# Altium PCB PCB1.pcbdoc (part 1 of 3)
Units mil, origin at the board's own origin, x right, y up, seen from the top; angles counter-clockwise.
Board outline 1393.7 x 1462.72 mil, 2 copper layers (Top Layer, Bottom Layer), stack 62.206 mil thick; 10 components, 35 nets, 86 pads, 11 vias.
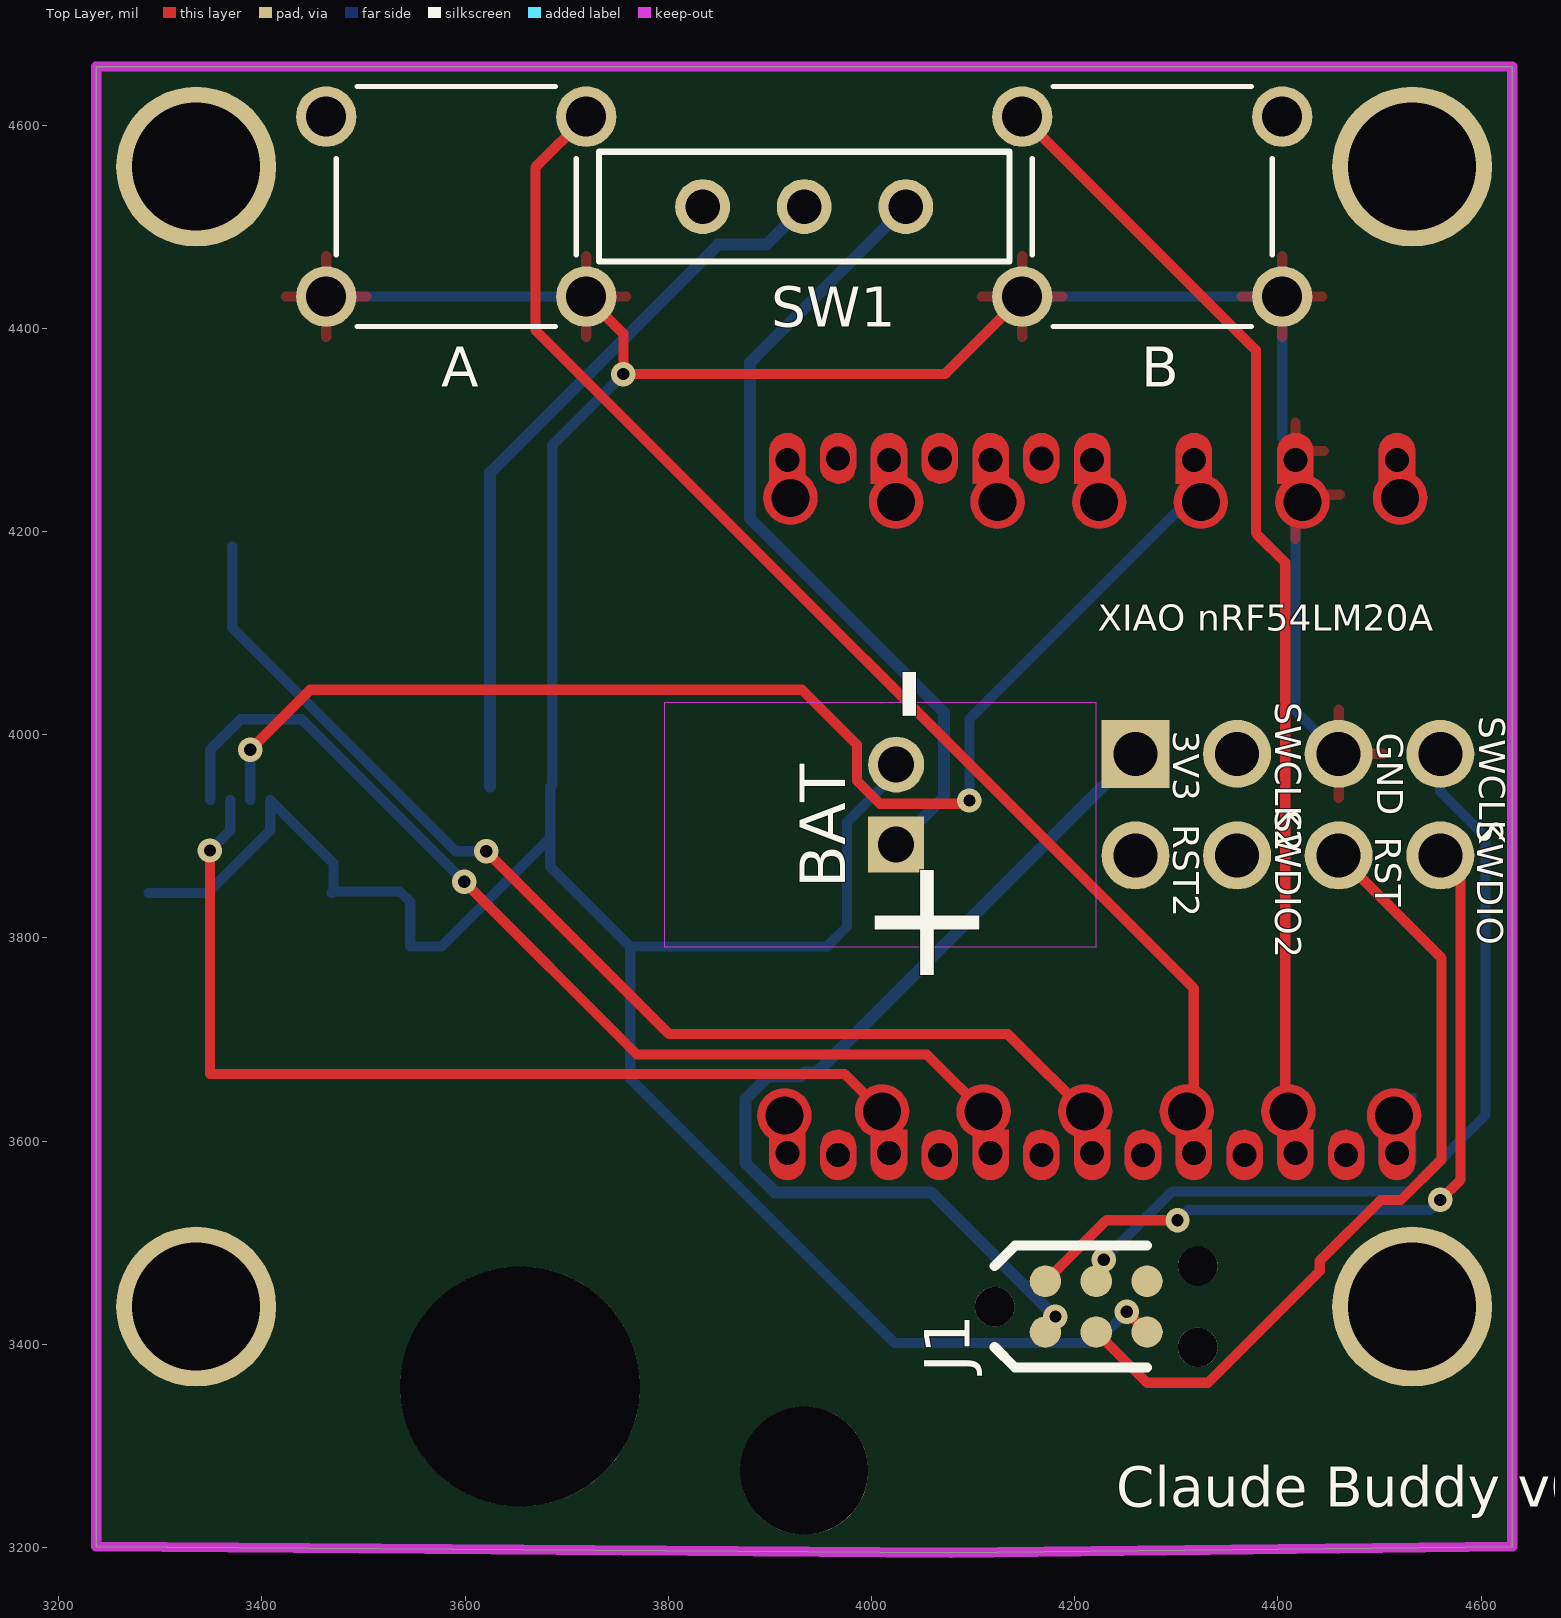
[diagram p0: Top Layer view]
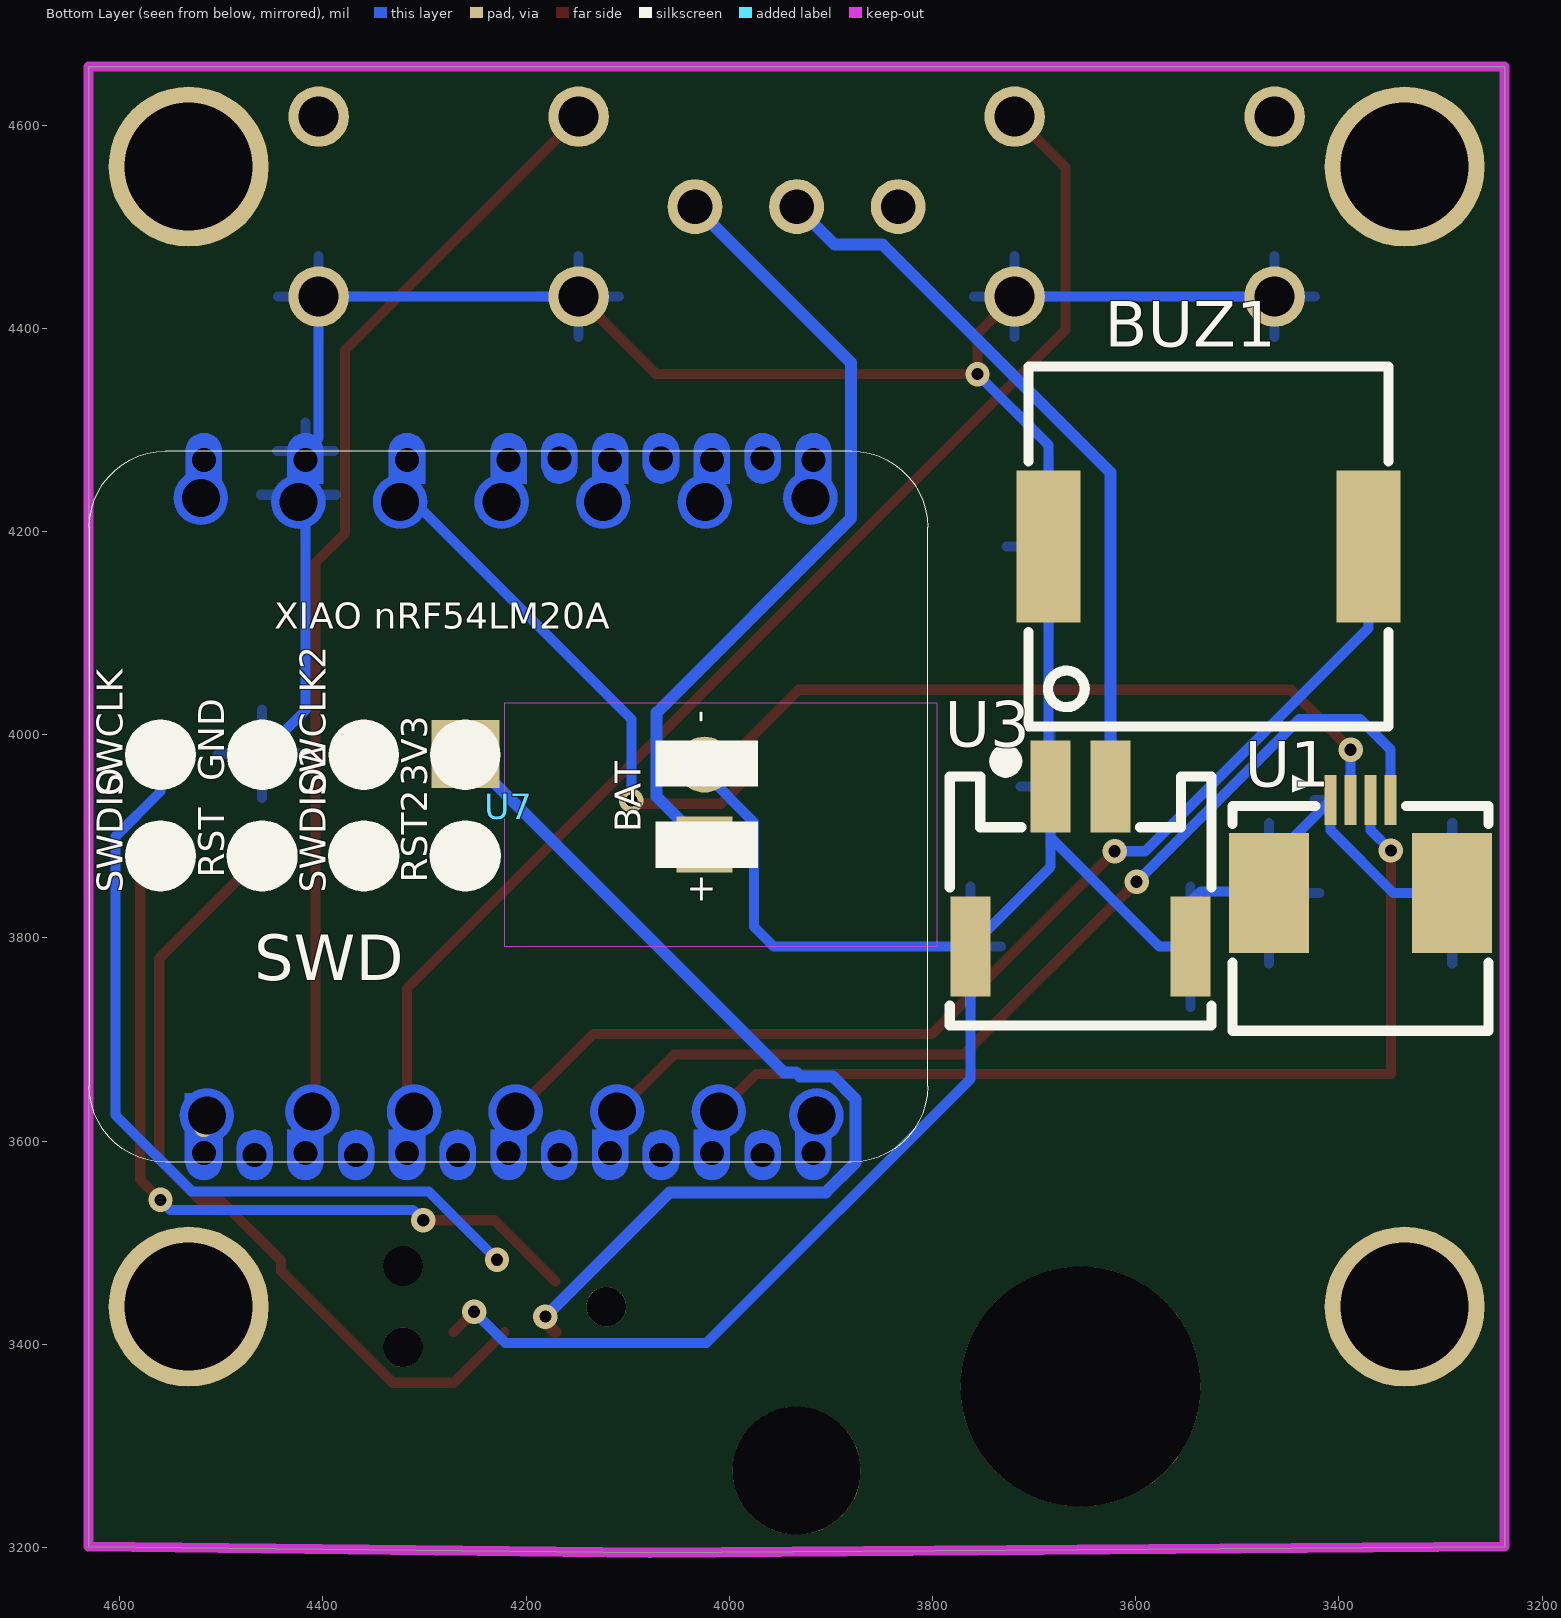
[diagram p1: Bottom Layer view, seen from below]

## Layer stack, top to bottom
Top Solder Mask Layer: solder mask 0.394, Dk 3.3
Top Layer: signal copper 1.379
Dielectric1: surface 59.449, FR4, Dk 4.5
Bottom Layer: signal copper 1.378
Bottom Solder Mask Layer: solder mask 0.394, Dk 3.3

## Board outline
3236.93,3200.79 3236.93,4657.48 4630.63,4657.48 4630.63,4165.35 4630.63,4047.24 4630.63,3811.02 4630.63,3692.91 4630.63,3200.79 4078.23,3194.76

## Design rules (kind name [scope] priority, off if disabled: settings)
BoardOutlineClearance copperThickness1oz [All] p0: genericclearance=10 ignorepadtopadclearanceinfootprint=FALSE except(0: Arc-SplitContinuation Track-SplitContinuation SMDPad-SplitContinuation THPad-SplitContinuation Via-SplitContinuation Fill-SplitContinuation Poly-SplitContinuation Region-SplitContinuation Text-SplitContinuation)
BoardOutlineClearance copperThickness2oz [All] p0: genericclearance=10 ignorepadtopadclearanceinfootprint=FALSE except(0: Arc-SplitContinuation Track-SplitContinuation SMDPad-SplitContinuation THPad-SplitContinuation Via-SplitContinuation Fill-SplitContinuation Poly-SplitContinuation Region-SplitContinuation Text-SplitContinuation)
BoardOutlineClearance otherClearance [All] p0: genericclearance=10 ignorepadtopadclearanceinfootprint=FALSE except(0: Arc-SplitContinuation Track-SplitContinuation SMDPad-SplitContinuation THPad-SplitContinuation Via-SplitContinuation Fill-SplitContinuation Poly-SplitContinuation Region-SplitContinuation Text-SplitContinuation)
Clearance copperThickness1oz [All] p1: gap=7 ignorepadtopadclearanceinfootprint=FALSE
Clearance copperThickness2oz [All] p1: gap=7 ignorepadtopadclearanceinfootprint=FALSE
Clearance otherClearance [All] p1: gap=7 ignorepadtopadclearanceinfootprint=FALSE
DiffPairsRouting differentialPair [All] p1: maxuncoupledlength=10 minlimit=6 maxlimit=Infinity mostfreqgap=6 toplayer_minwidth=5 toplayer_prefwidth=10 toplayer_maxwidth=100 bottomlayer_minwidth=5 bottomlayer_prefwidth=10 bottomlayer_maxwidth=100
PasteMaskExpansion pasteMaskExpansion [All] p1: expansion=0
PlaneConnect innerPlane [All] p1: planeconnectstyle=Relief reliefexpansion=20 reliefentries=4 reliefconductorwidth=10 reliefairgap=10
PolygonConnect copperRegion [All] p1: connectstyle=Relief reliefentries=4 reliefconductorwidth=10 polygonreliefangle="90 Angle" airgapwidth=10
RoutingVias viaSize [All] p1: viastyle="Through Hole" holewidth=12.0078 minholewidth=11.811 maxholewidth=248.0314 width=12.0078 minwidth=11.811 maxwidth=248.0314
SolderMaskExpansion solderMaskExpansion [IsVia] p1: useseparateexpansions=TRUE expansion=-1000 expansionbottom=-1000
SolderMaskExpansion solderMaskExpansion [All] p2: useseparateexpansions=TRUE expansion=2 expansionbottom=2
Width copperThickness1oz [All] p1: maxlimit=100 minlimit=5 preferedwidth=10
Width copperThickness2oz [All] p1: maxlimit=100 minlimit=8 preferedwidth=10
Width trackWidth1 [All] p1: maxlimit=100 minlimit=12 preferedwidth=12

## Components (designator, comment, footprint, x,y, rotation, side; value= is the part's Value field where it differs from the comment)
A "MJTP1230G" SW_MJTP1230G 3591.26,4519.69 r0 top locked
B "MJTP1230G" SW_MJTP1230G 4276.3,4519.69 r0 top locked
BAT "HX PZ2.0-1x2P ZZ" CB_HDR-TH_2P-P2.00-V-M 4024.33,3931.1 r90 top
BUZ1 "4kHz" BUZ-SMD_L9.0-W9.0_PKMCS0909E4000-R1 3528.27,4185.04 r180 bottom locked
J1 "TC2030-CTX-NL" TC2030-CTX-NL 4221.18,3437.01 r90 top locked
SW1 "09.03290.01" 09.03290_EAO 3933.78,4519.69 r270 top locked
SWD "PZ254V-12-8P" CB_HDR-TH_8P-P2.54-V-M-R2-C4-S2.54 4409.84,3931.1 r0 bottom locked
U1 "05A20L04P" FPC-SMD_4P-P0.50_05A20L4P 3378.66,3889.76 r180 bottom locked
U3 "ZX-ZH1.5-2PWT" CONN-SMD_2P-P1.50_ZX-ZH1.5-2PWT 3654.25,3870.08 r180 bottom locked
U7 "Seeed_Studio_XIAO_Series_XIAO-Add-On-Plus" Claude_buddy_Seeed_Studio_XIAO_Series:XIAO-Add-On-PRO 4217.24,3929.13 r0 bottom locked

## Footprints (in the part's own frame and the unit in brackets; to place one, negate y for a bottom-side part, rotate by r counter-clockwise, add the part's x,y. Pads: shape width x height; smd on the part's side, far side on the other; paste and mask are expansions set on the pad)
09.03290_EAO [mil]
  round 54 hole 34 paste+0 mask+0: 1(0,0) 2(0,-100) 3(0,100)
  silkscreen extent -54,-202 54,202
BUZ-SMD_L9.0-W9.0_PKMCS0909E4000-R1 [mm]
  rect 1.6x3.8 smd: 1(-4,0) 2(4,0)
  silkscreen extent -4.5,-4.5 4.5,4.5
CB_HDR-TH_2P-P2.00-V-M [mm]
  rect 1.4x1.4 hole 0.9: 1(-1,0)
  round 1.4 hole 0.9: 2(1,0)
CB_HDR-TH_8P-P2.54-V-M-R2-C4-S2.54 [mm]
  rect 1.7x1.7 hole 1.1: 1(-3.81,-1.27)
  round 1.7 hole 1.1: 2(-3.81,1.27) 3(-1.27,-1.27) 4(-1.27,1.27) 5(1.27,-1.27) 6(1.27,1.27) 7(3.81,-1.27) 8(3.81,1.27)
